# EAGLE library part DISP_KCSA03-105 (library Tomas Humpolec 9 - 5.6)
SURFACE MOUNT DISPLAY P/N: KCSA03-105 HYPER RED Features 0.3 INCH DIGIT HEIGHT. LOW CURRENT OPERATION. EXCELLENT CHARACTER APPEARANCE. I.C. COMPATIBLE. MECHANICALLY RUGGED. GRAY FACE,WHITE SEGMENT. PACKAGE : 550PCS / REEL. MOISTURE SENSITIVITY LEVEL : LEVEL 4. RoHS COMPLIANT. Description The Hyper Red source color devices are made with DH InGaAlP on GaAs substrate Light Emitting Diode. Electrical Characteristics Power dissipation 75 mW DC Forward Current 30 mA Peak Forward Current [1] 185 mA Reverse Voltage 5 V Operating/Storage Temperature -40°C To +85°C
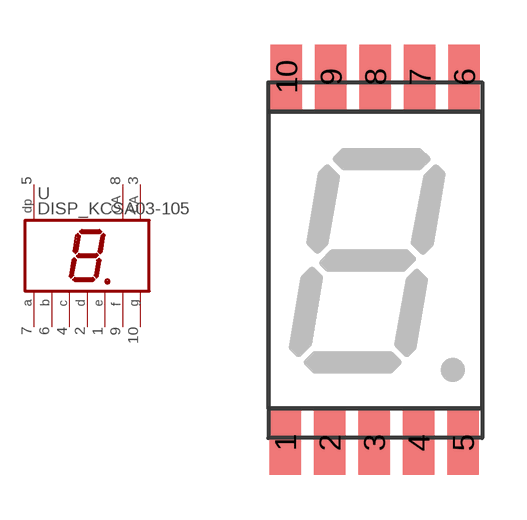
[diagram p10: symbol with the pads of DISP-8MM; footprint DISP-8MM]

Designator prefix -

## DISP_KCSA03-105SMD  [DISP-8MM]
1  E  pas
2  D  pas
3  CA  pas
4  C  pas
5  DP  pas
6  B  pas
7  A  pas
8  CA  pas
9  F  pas
10  G  pas

## Footprint DISP-8MM (pad centres in mm)
smd 1.067 x 2.184: 1 0.57,-1.16; 2 2.07,-1.16; 3 3.57,-1.16; 4 5.07,-1.16; 5 6.57,-1.16; 6 6.61,11.18; 7 5.11,11.18; 8 3.61,11.18; 9 2.11,11.18; 10 0.61,11.18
